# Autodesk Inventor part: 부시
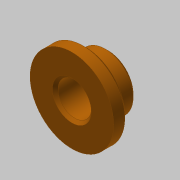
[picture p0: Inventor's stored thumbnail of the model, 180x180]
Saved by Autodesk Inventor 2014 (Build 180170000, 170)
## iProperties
Created: 2016-02
Part Number: 부시
Material: 스테인리스강
Document SubType Name: Modeling
Designer: mduedu
Density: 8.08 g/cm^3
Appearance: 주황색
Mass: 36.2061 g
Surface Area: 25.361 cm^2
Volume: 4.48096 cm^3
Author: mduedu
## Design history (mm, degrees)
sketch "스케치1"
  geometry: C1 r 15 at (0, 0); 1 further point
  constraints: 1 centre point, 1 coincident
  dimensions: "d0" = 30 diameter of C1
extrude "돌출1" new body sketch "스케치1" distance "d1" = 5; taper "d2" = 0 deg
sketch "스케치2"
  geometry: C1 r 10 at (0, 0); 1 further point
  constraints: 1 centre point, 1 coincident
  dimensions: "d3" = 20 diameter of C1
extrude "돌출2" join sketch "스케치2" distance "d4" = 8; taper "d5" = 0 deg
hole "구멍1" diameter "d8" = 12; stored, may be unused: countersink angle "d12" = 90 deg, drill point angle "d14" = 118 deg; dims "d9" = 6, "d10" = 4, "d11" = 2, "d13" = 8, "d15" = 10, "d16" = 10
chamfer "모따기1" distance "d17" = 1; stored, may be unused: second distance "d18" = 2, angle "d19" = 45 deg
chamfer "모따기2" distance "d20" = 1; stored, may be unused: second distance "d21" = 2, angle "d22" = 45 deg
chamfer "모따기3" distance "d23" = 1; stored, may be unused: second distance "d24" = 2, angle "d25" = 45 deg
node "솔리드1"
